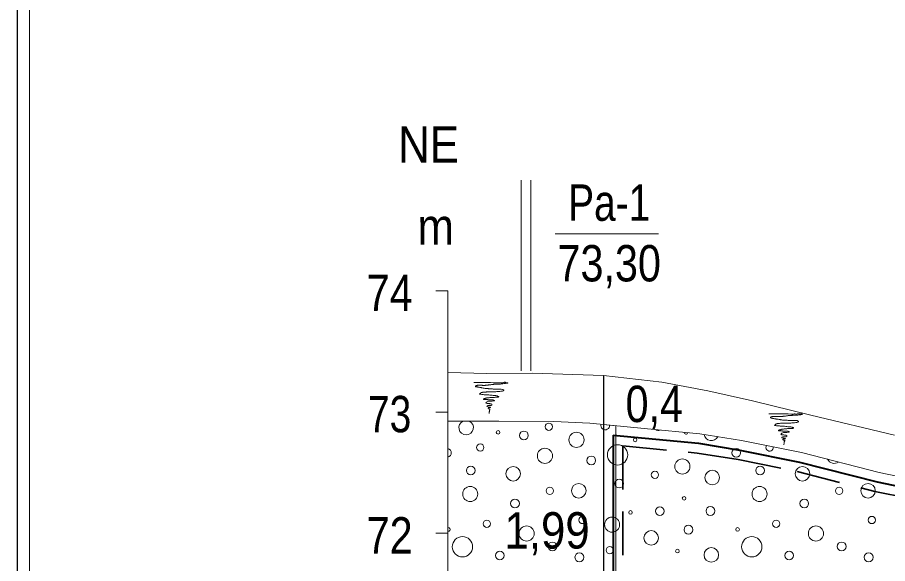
# Model space of a CAD drawing. Extents: x 640104 to 640970, y 6442278 to 6442689.
# Drawn here: x 640103.6 to 640175.4, y 6442438.2 to 6442483.3 of the extents above; entities that cross this region are included whole.
import ezdxf
from ezdxf.enums import TextEntityAlignment as Align

# ---------------------------------------------------------------- set-up
doc = ezdxf.new("R2010")
doc.units = 0
doc.header["$LTSCALE"] = 1.2
doc.linetypes.add('MEDIUM_DASHED', pattern=[4.5, 3, -1.5])
for name, color, linetype, lineweight in [('30', 7, 'Continuous', 13), ('31', 7, 'Continuous', 13), ('32', 7, 'Continuous', 25), ('33', 7, 'Continuous', 13), ('35', 7, 'Continuous', 35), ('40', 7, 'Continuous', 13), ('41', 7, 'Continuous', 13), ('50', 7, 'Continuous', 13)]:
    doc.layers.add(name, color=color, linetype=linetype, lineweight=lineweight)

msp = doc.modelspace()

# ---------------------------------------------------------------- linework, layer by layer
at = {"layer": '30'}
for p, q in [((640138.08, 6442460.75), (640139.08, 6442460.75)), ((640139.08, 6442300.75), (640139.08, 6442460.75)), ((640138.08, 6442450.75), (640139.08, 6442450.75)), ((640138.08, 6442440.75), (640139.08, 6442440.75))]:
    msp.add_line(p, q, dxfattribs=at)
at = {"layer": '31'}
for points in [[(640139.08, 6442454.02), (640142.3, 6442453.94), (640146.03, 6442453.96), (640151.92, 6442453.75), (640156.74, 6442453.2), (640160.52, 6442452.5), (640164.2, 6442451.68), (640169.01, 6442450.5), (640175.92, 6442448.83)], [(640139.08, 6442450), (640143.29, 6442450), (640147.83, 6442449.96), (640150.8, 6442449.83), (640155.27, 6442449.39), (640159.86, 6442448.96), (640163.31, 6442448.4), (640168.26, 6442447.4), (640174.67, 6442445.76), (640180.34, 6442444.59)]]:
    msp.add_lwpolyline(points, dxfattribs=at)
at = {"layer": '32', "lineweight": 13}
msp.add_line((640147.93, 6442465.44), (640156.44, 6442465.44), dxfattribs=at)
at = {"layer": '32'}
msp.add_line((640151.92, 6442453.75), (640151.92, 6442385.75), dxfattribs=at)
at = {"layer": '33'}
msp.add_lwpolyline([(640152.92, 6442423.75), (640152.92, 6442449.62), (640151.92, 6442449.72), (640151.92, 6442423.75), (640151.96, 6442423.75)], close=True, dxfattribs=at)
at = {"layer": '35', "lineweight": 13}
for p, q in [((640145.12, 6442454.14), (640145.12, 6442469.88)), ((640145.92, 6442454.14), (640145.92, 6442469.88))]:
    msp.add_line(p, q, dxfattribs=at)
at = {"layer": '35', "lineweight": 40}
msp.add_line((640152.72, 6442448.83), (640152.72, 6442392.46), dxfattribs=at)
at = {"layer": '35', "linetype": 'MEDIUM_DASHED'}
msp.add_line((640153.52, 6442447.95), (640153.52, 6442424.38), dxfattribs=at)
at = {"layer": '35', "lineweight": 40}
msp.add_lwpolyline([(640152.72, 6442448.83), (640159.76, 6442448.17), (640163.16, 6442447.61), (640168.08, 6442446.62), (640174.49, 6442444.98), (640180.16, 6442443.81)], dxfattribs=at)
at = {"layer": '35', "linetype": 'MEDIUM_DASHED'}
msp.add_lwpolyline([(640153.52, 6442447.95), (640159.65, 6442447.37), (640163.02, 6442446.83), (640167.9, 6442445.84), (640174.31, 6442444.2), (640179.98, 6442443.03)], dxfattribs=at)
at = {"layer": '40'}
for points in [[(640141.22, 6442453.18), (640141.26, 6442453.18), (640141.33, 6442453.18), (640141.4, 6442453.18), (640141.42, 6442453.19), (640141.49, 6442453.19), (640141.59, 6442453.19), (640141.81, 6442453.19), (640141.93, 6442453.19), (640141.95, 6442453.19), (640141.98, 6442453.19), (640142.03, 6442453.19), (640142.08, 6442453.19), (640142.15, 6442453.19), (640142.21, 6442453.19), (640142.25, 6442453.19), (640142.31, 6442453.19), (640142.35, 6442453.19), (640142.4, 6442453.19), (640142.46, 6442453.18), (640142.49, 6442453.18), (640142.54, 6442453.18), (640142.6, 6442453.18), (640142.83, 6442453.17), (640143.03, 6442453.16), (640143.1, 6442453.16), (640143.14, 6442453.16), (640143.16, 6442453.16), (640143.19, 6442453.16), (640143.24, 6442453.16), (640143.31, 6442453.17), (640143.34, 6442453.17), (640143.36, 6442453.17), (640143.38, 6442453.17), (640143.4, 6442453.17), (640143.45, 6442453.16), (640143.47, 6442453.16), (640143.51, 6442453.16), (640143.57, 6442453.17), (640143.61, 6442453.17), (640143.66, 6442453.18), (640143.68, 6442453.19), (640143.73, 6442453.19), (640143.75, 6442453.2), (640143.79, 6442453.2), (640143.82, 6442453.2), (640143.84, 6442453.19), (640143.87, 6442453.18), (640143.9, 6442453.17), (640143.92, 6442453.17)], [(640142.24, 6442452.96), (640142.22, 6442452.96), (640142.18, 6442452.96), (640142.15, 6442452.95), (640142.13, 6442452.95), (640142.11, 6442452.95), (640142.07, 6442452.95), (640142.04, 6442452.95), (640142.01, 6442452.95), (640141.96, 6442452.95), (640141.94, 6442452.95), (640141.9, 6442452.96), (640141.87, 6442452.96), (640141.85, 6442452.96), (640141.83, 6442452.96), (640141.79, 6442452.96), (640141.76, 6442452.96), (640141.71, 6442452.96), (640141.69, 6442452.96), (640141.67, 6442452.96), (640141.63, 6442452.96), (640141.6, 6442452.96), (640141.57, 6442452.96), (640141.55, 6442452.96), (640141.51, 6442452.96), (640141.48, 6442452.95), (640141.46, 6442452.93), (640141.43, 6442452.93), (640141.4, 6442452.92), (640141.39, 6442452.92), (640141.37, 6442452.91), (640141.35, 6442452.89), (640141.35, 6442452.87), (640141.35, 6442452.84), (640141.42, 6442452.84), (640141.46, 6442452.84), (640141.48, 6442452.82), (640141.51, 6442452.82), (640141.54, 6442452.81), (640141.55, 6442452.8), (640141.59, 6442452.8), (640141.63, 6442452.8), (640141.65, 6442452.79), (640141.7, 6442452.77), (640141.75, 6442452.76), (640141.79, 6442452.76), (640141.83, 6442452.76), (640141.86, 6442452.75), (640141.91, 6442452.74), (640141.99, 6442452.73)], [(640141.99, 6442452.73), (640142.08, 6442452.72), (640142.15, 6442452.7), (640142.19, 6442452.69), (640142.25, 6442452.68), (640142.31, 6442452.68), (640142.36, 6442452.68), (640142.4, 6442452.68), (640142.43, 6442452.66), (640142.49, 6442452.66), (640142.53, 6442452.66), (640142.59, 6442452.65), (640142.64, 6442452.65), (640142.69, 6442452.65), (640142.75, 6442452.65), (640142.81, 6442452.64), (640142.85, 6442452.64), (640142.87, 6442452.64), (640142.92, 6442452.64), (640142.97, 6442452.64), (640143.03, 6442452.64), (640143.09, 6442452.64), (640143.15, 6442452.64), (640143.19, 6442452.64), (640143.24, 6442452.64), (640143.27, 6442452.64), (640143.31, 6442452.64), (640143.35, 6442452.64), (640143.39, 6442452.64), (640143.43, 6442452.64), (640143.46, 6442452.63), (640143.55, 6442452.62), (640143.59, 6442452.6), (640143.63, 6442452.59), (640143.66, 6442452.58), (640143.68, 6442452.57), (640143.68, 6442452.55), (640143.67, 6442452.52), (640143.66, 6442452.52), (640143.64, 6442452.51), (640143.63, 6442452.49), (640143.59, 6442452.48), (640143.54, 6442452.47), (640143.44, 6442452.46), (640143.35, 6442452.44), (640143.31, 6442452.44), (640143.24, 6442452.44), (640143.19, 6442452.43), (640143.12, 6442452.43), (640143.03, 6442452.42), (640142.91, 6442452.42), (640142.79, 6442452.42)], [(640143.92, 6442453.17), (640143.95, 6442453.16), (640143.98, 6442453.16), (640144.01, 6442453.16), (640144.03, 6442453.15), (640144.01, 6442453.14), (640144.02, 6442453.15), (640143.99, 6442453.14), (640143.96, 6442453.13), (640143.92, 6442453.12), (640143.9, 6442453.12), (640143.87, 6442453.12), (640143.84, 6442453.12), (640143.82, 6442453.12), (640143.8, 6442453.1), (640143.76, 6442453.1), (640143.71, 6442453.09), (640143.69, 6442453.09), (640143.61, 6442453.08), (640143.58, 6442453.08), (640143.55, 6442453.08), (640143.52, 6442453.07), (640143.49, 6442453.07), (640143.47, 6442453.07), (640143.43, 6442453.06), (640143.4, 6442453.06), (640143.33, 6442453.06), (640143.29, 6442453.06), (640143.24, 6442453.06), (640143.19, 6442453.06), (640143.15, 6442453.05), (640143.11, 6442453.05), (640143.07, 6442453.04), (640143.03, 6442453.04), (640142.92, 6442453.04), (640142.9, 6442453.04), (640142.87, 6442453.04), (640142.83, 6442453.03), (640142.76, 6442453.02), (640142.71, 6442453.01), (640142.67, 6442453.01), (640142.61, 6442453), (640142.57, 6442453), (640142.54, 6442452.99), (640142.5, 6442452.99), (640142.48, 6442452.98), (640142.46, 6442452.98), (640142.42, 6442452.98), (640142.39, 6442452.97), (640142.36, 6442452.97), (640142.27, 6442452.96), (640142.24, 6442452.96)], [(640142.79, 6442452.42), (640142.74, 6442452.42), (640142.69, 6442452.42), (640142.63, 6442452.42), (640142.59, 6442452.42), (640142.55, 6442452.42), (640142.5, 6442452.42), (640142.44, 6442452.41), (640142.32, 6442452.41), (640142.27, 6442452.41), (640142.23, 6442452.4), (640142.18, 6442452.4), (640142.1, 6442452.39), (640142.01, 6442452.39), (640141.98, 6442452.38), (640141.94, 6442452.38), (640141.92, 6442452.37), (640141.9, 6442452.36), (640141.87, 6442452.36), (640141.85, 6442452.36), (640141.83, 6442452.35), (640141.81, 6442452.33), (640141.77, 6442452.31), (640141.75, 6442452.29), (640141.74, 6442452.28), (640141.71, 6442452.27), (640141.71, 6442452.25), (640141.69, 6442452.24), (640141.68, 6442452.22), (640141.7, 6442452.21), (640141.72, 6442452.21), (640141.76, 6442452.21), (640141.79, 6442452.21), (640141.87, 6442452.2), (640141.92, 6442452.2), (640141.99, 6442452.19), (640142.07, 6442452.18), (640142.11, 6442452.18), (640142.15, 6442452.16), (640142.19, 6442452.16), (640142.3, 6442452.16), (640142.39, 6442452.16), (640142.46, 6442452.16), (640142.53, 6442452.15), (640142.63, 6442452.14), (640142.72, 6442452.14), (640142.8, 6442452.12), (640142.86, 6442452.12), (640142.92, 6442452.12), (640142.98, 6442452.11)], [(640142.98, 6442452.11), (640143.01, 6442452.11), (640143.04, 6442452.1), (640143.1, 6442452.08), (640143.15, 6442452.08), (640143.18, 6442452.06), (640143.21, 6442452.05), (640143.25, 6442452.04), (640143.27, 6442452.04), (640143.27, 6442452), (640143.26, 6442452), (640143.24, 6442451.99), (640143.22, 6442451.98), (640143.14, 6442451.97), (640143.1, 6442451.97), (640143.07, 6442451.97), (640143.03, 6442451.97), (640142.97, 6442451.97), (640142.91, 6442451.96), (640142.88, 6442451.96), (640142.85, 6442451.96), (640142.76, 6442451.96), (640142.71, 6442451.95), (640142.69, 6442451.95), (640142.65, 6442451.95), (640142.63, 6442451.94), (640142.59, 6442451.94), (640142.53, 6442451.94), (640142.48, 6442451.93), (640142.43, 6442451.92), (640142.39, 6442451.92), (640142.36, 6442451.92), (640142.33, 6442451.92), (640142.31, 6442451.91), (640142.27, 6442451.91), (640142.26, 6442451.89), (640142.22, 6442451.88), (640142.2, 6442451.88), (640142.18, 6442451.88), (640142.15, 6442451.87), (640142.11, 6442451.86), (640142.07, 6442451.85), (640142.03, 6442451.84), (640142.02, 6442451.82), (640142.02, 6442451.79), (640142.04, 6442451.79), (640142.09, 6442451.79), (640142.15, 6442451.78), (640142.21, 6442451.78), (640142.24, 6442451.78), (640142.31, 6442451.77), (640142.35, 6442451.77)], [(640142.35, 6442451.77), (640142.36, 6442451.76), (640142.39, 6442451.76), (640142.43, 6442451.76), (640142.47, 6442451.76), (640142.5, 6442451.76), (640142.57, 6442451.76), (640142.63, 6442451.76), (640142.65, 6442451.76), (640142.68, 6442451.76), (640142.71, 6442451.76), (640142.75, 6442451.76), (640142.79, 6442451.75), (640142.82, 6442451.73), (640142.85, 6442451.72), (640142.88, 6442451.72), (640142.91, 6442451.71), (640142.91, 6442451.68), (640142.83, 6442451.66), (640142.72, 6442451.65), (640142.68, 6442451.65), (640142.61, 6442451.64), (640142.57, 6442451.64), (640142.52, 6442451.64), (640142.47, 6442451.64), (640142.43, 6442451.64), (640142.38, 6442451.62), (640142.32, 6442451.6), (640142.31, 6442451.58), (640142.27, 6442451.56), (640142.26, 6442451.55), (640142.24, 6442451.53), (640142.23, 6442451.51), (640142.22, 6442451.48), (640142.23, 6442451.48), (640142.27, 6442451.47), (640142.31, 6442451.45), (640142.4, 6442451.45), (640142.47, 6442451.44), (640142.51, 6442451.44), (640142.55, 6442451.43), (640142.59, 6442451.43), (640142.65, 6442451.42), (640142.71, 6442451.4), (640142.71, 6442451.36), (640142.71, 6442451.34), (640142.7, 6442451.32), (640142.65, 6442451.28), (640142.63, 6442451.28), (640142.59, 6442451.28), (640142.53, 6442451.28), (640142.47, 6442451.28), (640142.43, 6442451.28), (640142.37, 6442451.28), (640142.31, 6442451.26), (640142.31, 6442451.24), (640142.3, 6442451.22), (640142.31, 6442451.2), (640142.33, 6442451.2), (640142.41, 6442451.17), (640142.47, 6442451.16), (640142.5, 6442451.16), (640142.54, 6442451.15), (640142.58, 6442451.14), (640142.6, 6442451.12), (640142.59, 6442451.12), (640142.55, 6442451.12), (640142.5, 6442451.11), (640142.43, 6442451.1), (640142.41, 6442451.1), (640142.39, 6442451.09), (640142.39, 6442451.06), (640142.4, 6442451.04), (640142.42, 6442451.04), (640142.44, 6442451.02), (640142.47, 6442451.01), (640142.51, 6442451), (640142.55, 6442451), (640142.55, 6442450.96), (640142.54, 6442450.95), (640142.53, 6442450.92), (640142.51, 6442450.9), (640142.5, 6442450.88), (640142.5, 6442450.85), (640142.5, 6442450.82), (640142.5, 6442450.8), (640142.49, 6442450.77), (640142.49, 6442450.74), (640142.48, 6442450.72), (640142.47, 6442450.69), (640142.47, 6442450.67), (640142.47, 6442450.64), (640142.47, 6442450.63), (640142.47, 6442450.65)], [(640165.55, 6442450.6), (640165.59, 6442450.6), (640165.66, 6442450.6), (640165.73, 6442450.6), (640165.75, 6442450.61), (640165.82, 6442450.61), (640165.92, 6442450.61), (640166.14, 6442450.61), (640166.26, 6442450.61), (640166.28, 6442450.61), (640166.31, 6442450.61), (640166.36, 6442450.61), (640166.41, 6442450.61), (640166.48, 6442450.61), (640166.54, 6442450.61), (640166.58, 6442450.61), (640166.64, 6442450.61), (640166.68, 6442450.61), (640166.73, 6442450.61), (640166.79, 6442450.6), (640166.82, 6442450.6), (640166.87, 6442450.6), (640166.93, 6442450.6), (640167.16, 6442450.59), (640167.36, 6442450.58), (640167.43, 6442450.58), (640167.47, 6442450.58), (640167.49, 6442450.58), (640167.52, 6442450.58), (640167.57, 6442450.58), (640167.64, 6442450.59), (640167.67, 6442450.59), (640167.69, 6442450.59), (640167.71, 6442450.59), (640167.73, 6442450.59), (640167.78, 6442450.58), (640167.8, 6442450.58), (640167.84, 6442450.58), (640167.9, 6442450.59), (640167.94, 6442450.59), (640167.99, 6442450.6), (640168.01, 6442450.61), (640168.06, 6442450.61), (640168.08, 6442450.61), (640168.12, 6442450.61), (640168.15, 6442450.61), (640168.17, 6442450.61), (640168.2, 6442450.6), (640168.23, 6442450.59), (640168.25, 6442450.59)], [(640168.25, 6442450.59), (640168.28, 6442450.58), (640168.31, 6442450.58), (640168.34, 6442450.58), (640168.36, 6442450.57), (640168.34, 6442450.56), (640168.35, 6442450.57), (640168.32, 6442450.56), (640168.29, 6442450.55), (640168.25, 6442450.54), (640168.23, 6442450.54), (640168.2, 6442450.54), (640168.17, 6442450.53), (640168.15, 6442450.53), (640168.13, 6442450.52), (640168.09, 6442450.52), (640168.04, 6442450.51), (640168.02, 6442450.51), (640167.94, 6442450.5), (640167.91, 6442450.49), (640167.88, 6442450.49), (640167.85, 6442450.49), (640167.82, 6442450.49), (640167.8, 6442450.49), (640167.76, 6442450.48), (640167.73, 6442450.48), (640167.66, 6442450.48), (640167.62, 6442450.48), (640167.57, 6442450.48), (640167.52, 6442450.48), (640167.48, 6442450.47), (640167.44, 6442450.47), (640167.4, 6442450.46), (640167.36, 6442450.46), (640167.25, 6442450.46), (640167.23, 6442450.46), (640167.2, 6442450.45), (640167.16, 6442450.45), (640167.09, 6442450.44), (640167.04, 6442450.43), (640167, 6442450.43), (640166.94, 6442450.42), (640166.9, 6442450.42), (640166.87, 6442450.41), (640166.83, 6442450.41), (640166.81, 6442450.4), (640166.79, 6442450.4), (640166.75, 6442450.4), (640166.72, 6442450.39), (640166.69, 6442450.39), (640166.6, 6442450.38), (640166.57, 6442450.38)], [(640166.57, 6442450.38), (640166.55, 6442450.37), (640166.51, 6442450.37), (640166.48, 6442450.37), (640166.46, 6442450.37), (640166.44, 6442450.37), (640166.4, 6442450.37), (640166.37, 6442450.37), (640166.34, 6442450.37), (640166.29, 6442450.37), (640166.27, 6442450.37), (640166.23, 6442450.37), (640166.2, 6442450.37), (640166.18, 6442450.37), (640166.16, 6442450.37), (640166.12, 6442450.37), (640166.09, 6442450.37), (640166.04, 6442450.37), (640166.02, 6442450.37), (640166, 6442450.37), (640165.96, 6442450.37), (640165.93, 6442450.37), (640165.9, 6442450.37), (640165.88, 6442450.37), (640165.84, 6442450.37), (640165.81, 6442450.37), (640165.79, 6442450.35), (640165.76, 6442450.35), (640165.73, 6442450.34), (640165.72, 6442450.33), (640165.7, 6442450.33), (640165.68, 6442450.31), (640165.68, 6442450.29), (640165.68, 6442450.26), (640165.75, 6442450.25), (640165.79, 6442450.25), (640165.81, 6442450.24), (640165.84, 6442450.24), (640165.87, 6442450.23), (640165.88, 6442450.22), (640165.92, 6442450.22), (640165.96, 6442450.21), (640165.98, 6442450.21), (640166.03, 6442450.19), (640166.08, 6442450.18), (640166.12, 6442450.18), (640166.16, 6442450.17), (640166.19, 6442450.17), (640166.24, 6442450.16), (640166.32, 6442450.15)], [(640167.12, 6442449.84), (640167.07, 6442449.84), (640167.02, 6442449.84), (640166.96, 6442449.84), (640166.92, 6442449.84), (640166.88, 6442449.84), (640166.83, 6442449.84), (640166.77, 6442449.83), (640166.65, 6442449.83), (640166.6, 6442449.83), (640166.56, 6442449.82), (640166.51, 6442449.82), (640166.43, 6442449.81), (640166.34, 6442449.81), (640166.31, 6442449.8), (640166.27, 6442449.8), (640166.25, 6442449.79), (640166.23, 6442449.78), (640166.2, 6442449.78), (640166.18, 6442449.77), (640166.16, 6442449.77), (640166.14, 6442449.75), (640166.1, 6442449.73), (640166.08, 6442449.71), (640166.07, 6442449.69), (640166.04, 6442449.69), (640166.04, 6442449.67), (640166.02, 6442449.65), (640166.01, 6442449.64), (640166.03, 6442449.63), (640166.05, 6442449.63), (640166.09, 6442449.63), (640166.12, 6442449.63), (640166.2, 6442449.62), (640166.25, 6442449.61), (640166.32, 6442449.61), (640166.4, 6442449.6), (640166.44, 6442449.6), (640166.48, 6442449.58), (640166.52, 6442449.58), (640166.63, 6442449.58), (640166.72, 6442449.58), (640166.79, 6442449.57), (640166.86, 6442449.57), (640166.96, 6442449.56), (640167.05, 6442449.56), (640167.13, 6442449.53), (640167.19, 6442449.53), (640167.25, 6442449.53), (640167.31, 6442449.53)], [(640166.32, 6442450.15), (640166.41, 6442450.13), (640166.48, 6442450.12), (640166.52, 6442450.11), (640166.58, 6442450.1), (640166.64, 6442450.1), (640166.69, 6442450.09), (640166.73, 6442450.09), (640166.76, 6442450.08), (640166.82, 6442450.08), (640166.86, 6442450.08), (640166.92, 6442450.07), (640166.97, 6442450.07), (640167.02, 6442450.07), (640167.08, 6442450.07), (640167.14, 6442450.06), (640167.18, 6442450.06), (640167.2, 6442450.06), (640167.25, 6442450.06), (640167.3, 6442450.06), (640167.36, 6442450.06), (640167.42, 6442450.06), (640167.48, 6442450.06), (640167.52, 6442450.06), (640167.57, 6442450.06), (640167.6, 6442450.06), (640167.64, 6442450.06), (640167.68, 6442450.06), (640167.72, 6442450.05), (640167.76, 6442450.05), (640167.79, 6442450.05), (640167.88, 6442450.04), (640167.92, 6442450.02), (640167.96, 6442450.01), (640167.99, 6442450), (640168.01, 6442449.99), (640168.01, 6442449.97), (640168, 6442449.94), (640167.99, 6442449.93), (640167.97, 6442449.93), (640167.96, 6442449.91), (640167.92, 6442449.9), (640167.87, 6442449.89), (640167.77, 6442449.88), (640167.68, 6442449.86), (640167.64, 6442449.85), (640167.57, 6442449.85), (640167.52, 6442449.85), (640167.45, 6442449.85), (640167.36, 6442449.84), (640167.24, 6442449.84), (640167.12, 6442449.84)], [(640167.31, 6442449.53), (640167.34, 6442449.53), (640167.37, 6442449.52), (640167.43, 6442449.5), (640167.48, 6442449.49), (640167.51, 6442449.48), (640167.54, 6442449.47), (640167.58, 6442449.46), (640167.6, 6442449.45), (640167.6, 6442449.42), (640167.59, 6442449.41), (640167.57, 6442449.41), (640167.55, 6442449.4), (640167.47, 6442449.39), (640167.43, 6442449.39), (640167.4, 6442449.39), (640167.36, 6442449.39), (640167.3, 6442449.39), (640167.24, 6442449.38), (640167.21, 6442449.38), (640167.18, 6442449.38), (640167.09, 6442449.38), (640167.04, 6442449.37), (640167.02, 6442449.37), (640166.98, 6442449.37), (640166.96, 6442449.36), (640166.92, 6442449.36), (640166.86, 6442449.36), (640166.81, 6442449.35), (640166.76, 6442449.34), (640166.72, 6442449.33), (640166.69, 6442449.33), (640166.66, 6442449.33), (640166.64, 6442449.33), (640166.6, 6442449.33), (640166.59, 6442449.31), (640166.55, 6442449.3), (640166.53, 6442449.29), (640166.51, 6442449.29), (640166.48, 6442449.29), (640166.44, 6442449.28), (640166.4, 6442449.27), (640166.36, 6442449.25), (640166.35, 6442449.24), (640166.35, 6442449.21), (640166.37, 6442449.21), (640166.42, 6442449.21), (640166.48, 6442449.2), (640166.54, 6442449.2), (640166.57, 6442449.2), (640166.64, 6442449.19), (640166.68, 6442449.19)], [(640166.68, 6442449.19), (640166.69, 6442449.18), (640166.72, 6442449.18), (640166.76, 6442449.18), (640166.8, 6442449.18), (640166.83, 6442449.18), (640166.9, 6442449.17), (640166.96, 6442449.17), (640166.98, 6442449.17), (640167.01, 6442449.17), (640167.04, 6442449.17), (640167.08, 6442449.17), (640167.12, 6442449.17), (640167.15, 6442449.15), (640167.18, 6442449.14), (640167.21, 6442449.13), (640167.24, 6442449.13), (640167.24, 6442449.09), (640167.16, 6442449.08), (640167.05, 6442449.07), (640167.01, 6442449.07), (640166.94, 6442449.06), (640166.9, 6442449.06), (640166.85, 6442449.06), (640166.8, 6442449.05), (640166.76, 6442449.05), (640166.71, 6442449.04), (640166.65, 6442449.01), (640166.64, 6442449), (640166.6, 6442448.98), (640166.59, 6442448.97), (640166.57, 6442448.95), (640166.56, 6442448.93), (640166.55, 6442448.9), (640166.56, 6442448.89), (640166.6, 6442448.89), (640166.64, 6442448.87), (640166.73, 6442448.87), (640166.8, 6442448.86), (640166.84, 6442448.85), (640166.88, 6442448.85), (640166.92, 6442448.85), (640166.98, 6442448.84), (640167.04, 6442448.81), (640167.04, 6442448.78), (640167.04, 6442448.76), (640167.03, 6442448.74), (640166.98, 6442448.7), (640166.96, 6442448.69), (640166.92, 6442448.69), (640166.86, 6442448.69), (640166.8, 6442448.69), (640166.76, 6442448.69), (640166.7, 6442448.69), (640166.64, 6442448.68), (640166.64, 6442448.65), (640166.63, 6442448.64), (640166.64, 6442448.62), (640166.66, 6442448.61), (640166.74, 6442448.59), (640166.8, 6442448.58), (640166.83, 6442448.57), (640166.87, 6442448.57), (640166.91, 6442448.56), (640166.93, 6442448.54), (640166.92, 6442448.53), (640166.88, 6442448.53), (640166.83, 6442448.53), (640166.76, 6442448.52), (640166.74, 6442448.52), (640166.72, 6442448.51), (640166.72, 6442448.48), (640166.73, 6442448.46), (640166.75, 6442448.45), (640166.77, 6442448.44), (640166.8, 6442448.43), (640166.84, 6442448.42), (640166.88, 6442448.41), (640166.88, 6442448.38), (640166.87, 6442448.37), (640166.86, 6442448.34), (640166.84, 6442448.32), (640166.83, 6442448.3), (640166.83, 6442448.27), (640166.83, 6442448.24), (640166.83, 6442448.21), (640166.82, 6442448.19), (640166.82, 6442448.16), (640166.81, 6442448.14), (640166.8, 6442448.11), (640166.8, 6442448.09), (640166.8, 6442448.05), (640166.8, 6442448.05), (640166.8, 6442448.07)]]:
    msp.add_lwpolyline(points, dxfattribs=at)
at = {"layer": '41'}
for centre, radius in [((640147.408, 6442449.536), 0.3), ((640143.22, 6442449.071), 0.15), ((640145.349, 6442448.824), 0.36), ((640149.684, 6442448.455), 0.624), ((640154.528, 6442448.45), 0.15), ((640141.747, 6442447.829), 0.3), ((640147.082, 6442447.135), 0.624), ((640153.076, 6442447.212), 0.835), ((640162.867, 6442447.383), 0.36), ((640150.908, 6442446.759), 0.36), ((640158.422, 6442446.257), 0.624), ((640140.962, 6442445.921), 0.36), ((640144.462, 6442445.654), 0.6), ((640164.831, 6442445.921), 0.36), ((640168.331, 6442445.654), 0.6), ((640156.157, 6442445.573), 0.3), ((640160.888, 6442445.342), 0.6), ((640149.872, 6442444.259), 0.6), ((640153.215, 6442444.845), 0.36), ((640173.741, 6442444.259), 0.6), ((640140.921, 6442443.988), 0.624), ((640147.486, 6442444.256), 0.3), ((640164.79, 6442443.988), 0.624), ((640171.355, 6442444.256), 0.3), ((640144.612, 6442443.2), 0.36), ((640158.56, 6442443.635), 0.15), ((640168.481, 6442443.2), 0.36), ((640154.141, 6442442.468), 0.15), ((640156.564, 6442442.578), 0.36), ((640160.731, 6442442.588), 0.36), ((640142.29, 6442441.535), 0.3), ((640150.184, 6442441.844), 0.3), ((640152.623, 6442441.464), 0.624), ((640166.159, 6442441.535), 0.3), ((640174.053, 6442441.844), 0.3), ((640145.572, 6442440.728), 0.624), ((640158.917, 6442441.047), 0.36), ((640162.979, 6442441.07), 0.15), ((640169.441, 6442440.728), 0.624), ((640140.28, 6442439.641), 0.838), ((640155.848, 6442440.371), 0.6), ((640164.149, 6442439.641), 0.838), ((640147.696, 6442439.67), 0.36), ((640152.431, 6442439.36), 0.3), ((640171.565, 6442439.67), 0.36), ((640143.359, 6442438.919), 0.36), ((640149.923, 6442438.767), 0.36), ((640158.017, 6442439.282), 0.15), ((640160.81, 6442438.97), 0.6), ((640167.228, 6442438.919), 0.36), ((640173.792, 6442438.767), 0.36)]:
    msp.add_circle(centre, radius, dxfattribs=at)
for centre, radius, start, end in [((640140.583, 6442449.461), 0.6, 114.98733, 65.01267), ((640152.06, 6442449.641), 0.36, 163.89986, 4.85665), ((640156.421, 6442449.584), 0.36, 231.05558, 298.23876), ((640158.716, 6442449.071), 0.15, 175.77713, 353.51722), ((640160.81, 6442448.993), 0.6, 188.64737, 332.91229), ((640138.998, 6442447.383), 0.36, 283.33012, 76.66988), ((640165.616, 6442447.829), 0.3, 148.37594, 8.78169), ((640170.951, 6442447.135), 0.624, 206.61799, 304.73399), ((640139.11, 6442441.07), 0.15, 258.96928, 101.03073)]:
    msp.add_arc(centre, radius, start, end, dxfattribs=at)
at = {"layer": '50', "lineweight": 25}
msp.add_lwpolyline([(640103.56, 6442688.99), (640970.3, 6442688.99), (640970.3, 6442282.54), (640103.56, 6442282.54)], close=True, dxfattribs=at)
at = {"layer": '50'}
msp.add_lwpolyline([(640104.56, 6442687.99), (640969.3, 6442687.99), (640969.3, 6442283.54), (640104.56, 6442283.54)], close=True, dxfattribs=at)

# ---------------------------------------------------------------- texts
at = {"layer": '30'}
for s, width, p in [('NE', 0.9, (640137.48, 6442471.31)), ('m', 0.9, (640138.07, 6442464.54)), ('74', 0.85, (640134.27, 6442459.08)), ('73', 0.8, (640134.27, 6442449.08)), ('72', 0.85, (640134.27, 6442439.08))]:
    msp.add_text(s, height=3, dxfattribs=dict(at, width=width)).set_placement(p, align=Align.CENTER)
at = {"layer": '32'}
for s, width, p in [('Pa-1', 0.8, (640152.385, 6442466.52)), ('73,30', 0.85, (640152.385, 6442461.52)), ('0,4', 0.85, (640156.105, 6442449.92))]:
    msp.add_text(s, height=3, dxfattribs=dict(at, width=width)).set_placement(p, align=Align.CENTER)
at = {"layer": '33', "width": 0.9}
msp.add_text('1,99', height=3, dxfattribs=at).set_placement((640147.26, 6442439.49), align=Align.CENTER)

doc.saveas('drawing.dxf')
